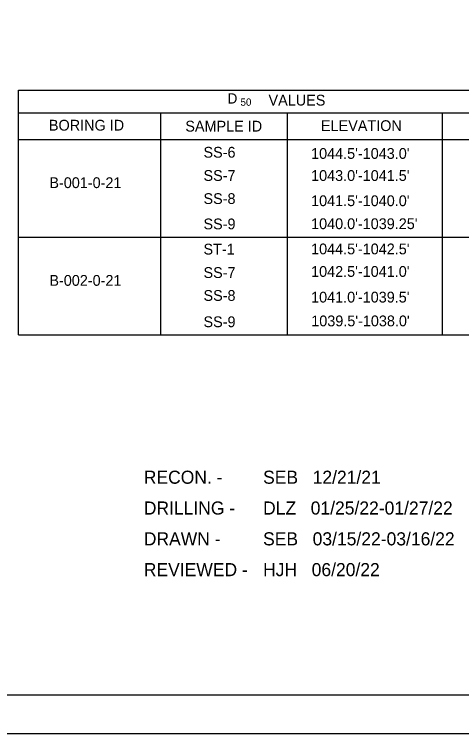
# Model space of a CAD drawing. Extents: x -5.4 to 49.9, y 13.2 to 48.4.
# Drawn here: x 26.26 to 32.07, y 26.43 to 35.77 of the extents above; entities that cross this region are included whole.
import ezdxf

# ---------------------------------------------------------------- set-up
doc = ezdxf.new("R2010")
doc.units = 0
for name, color, linetype in [('SH_Border', 7, 'Continuous'), ('SH_Cut_Line', 7, 'Continuous'), ('SH_Data', 7, 'Continuous'), ('SH_Text', 7, 'Continuous')]:
    doc.layers.add(name, color=color, linetype=linetype)

msp = doc.modelspace()

# ---------------------------------------------------------------- linework, layer by layer
at = {"layer": 'SH_Border'}
msp.add_lwpolyline([(4.2889, 47.9288), (36.2889, 47.9288), (36.2889, 26.9288), (4.2889, 26.9288)], close=True, dxfattribs=at)
at = {"layer": 'SH_Cut_Line'}
msp.add_line((29.1791, 34.6767), (29.1791, 34.6767), dxfattribs=at)
msp.add_lwpolyline([(2.7889, 26.4288), (36.7889, 26.4288), (36.7889, 48.4288), (2.7889, 48.4288)], close=True, dxfattribs=at)
at = {"layer": 'SH_Data'}
for p, q in [((26.3104, 32.876), (26.3104, 34.7835)), ((26.3104, 34.7835), (33.4089, 34.7835)), ((26.3104, 34.4909), (33.4089, 34.4909)), ((28.1588, 32.876), (28.1588, 34.4888)), ((29.806, 32.876), (29.806, 34.4905)), ((31.8218, 32.876), (31.8218, 34.4834)), ((26.3104, 34.1435), (33.4089, 34.1435)), ((26.3104, 31.6069), (26.3104, 32.8793)), ((26.3104, 32.876), (33.4089, 32.876)), ((28.1588, 31.6069), (28.1588, 32.876)), ((29.806, 31.6069), (29.806, 32.876)), ((31.8218, 31.607), (31.8218, 32.876)), ((26.3104, 31.6069), (33.4089, 31.6069))]:
    msp.add_line(p, q, dxfattribs=at)

# ---------------------------------------------------------------- texts
at = {"layer": 'SH_Cut_Line'}
for s, height, p in [('D', 0.133, (29.0263, 34.6102)), ('50', 0.095, (29.1958, 34.5817))]:
    msp.add_text(s, height=height, dxfattribs=at).set_placement(p)
at = {"layer": 'SH_Text'}
for s, height, p in [('VALUES', 0.14, (29.5595, 34.5845)), ('BORING ID', 0.14, (26.7056, 34.2592)), ('SAMPLE ID', 0.14, (28.4785, 34.2468)), ('ELEVATION', 0.14, (30.241, 34.2537)), ('SS-6', 0.14, (28.7144, 33.908)), ("1044.5'-1043.0'", 0.14, (30.1129, 33.8924)), ('SS-7', 0.14, (28.7144, 33.6062)), ("1043.0'-1041.5'", 0.14, (30.1129, 33.6058)), ('B-001-0-21', 0.14, (26.7117, 33.513)), ('SS-8', 0.14, (28.7144, 33.3064)), ("1041.5'-1040.0'", 0.14, (30.1129, 33.2783)), ('SS-9', 0.14, (28.7144, 32.9775)), ("1040.0'-1039.25'", 0.14, (30.1129, 32.9801)), ('ST-1', 0.14, (28.7144, 32.65)), ("1044.5'-1042.5'", 0.14, (30.1129, 32.6526)), ("1042.5'-1041.0'", 0.14, (30.1129, 32.3601)), ('SS-7', 0.14, (28.7144, 32.3459)), ('B-002-0-21', 0.14, (26.7117, 32.2439)), ('SS-8', 0.14, (28.7144, 32.0484)), ("1041.0'-1039.5'", 0.14, (30.1129, 32.0268)), ('SS-9', 0.14, (28.7144, 31.7067)), ("1039.5'-1038.0'", 0.14, (30.1149, 31.7181)), ('RECON. -', 0.17, (27.9388, 29.6733)), ('SEB   12/21/21           ', 0.17, (29.4888, 29.6733)), ('DRILLING -', 0.17, (27.9388, 29.2733)), ('DLZ   01/25/22-01/27/22  ', 0.17, (29.4888, 29.2733)), ('SEB   03/15/22-03/16/22                 ', 0.17, (29.4888, 28.8733)), ('DRAWN -', 0.17, (27.9388, 28.8733)), ('REVIEWED -', 0.17, (27.9388, 28.4733)), ('HJH   06/20/22                          ', 0.17, (29.4888, 28.4733))]:
    msp.add_text(s, height=height, dxfattribs=at).set_placement(p)

doc.saveas('drawing.dxf')
